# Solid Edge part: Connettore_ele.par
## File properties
Author: f_grande
Template: Normal.par
Last saved by: f_grande
Revision: 2
Application: Solid Edge
Material: PVC
Stile della faccia: Marroncino
Stile di riempimento: ANSI34(Plastica)
Stile virtuale: Marroncino (lucido)
Coef. of Thermal Exp: 0.0
Thermal Conductivity: 1.5
Specific Heat: 0.0
Modulus of Elasticity: 2757902.8
Poisson's Ratio: 0.4
Yield Stress: 6894757.0
Ultimate Stress: 0.0
Elongation: 0.0
Tipo di contenuto documento: 0
Densità: 1385,000 kg/m^3
Precisione: 0,990
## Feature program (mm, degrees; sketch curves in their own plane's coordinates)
sketch for "unnamed Protrusion 1" plane through (0, 0, 0) normal (0, 0, 1) x-axis (1, 0, 0)
  circle centre (0, 0) radius 10
extrude "unnamed Protrusion 1" add finite 10 along +normal
sketch for "unnamed RevolvedProtrusion 1" plane through (0, 0, 0) normal (0, -1, 0) x-axis (1, 0, 0)
  line (5.0499, 10) -> (12.8549, 10)
  line (12.8549, 14) -> (12.8549, 10)
  line (12.8549, 14) -> (9.6383, 14)
  arc centre (-66.7577, 14) radius 76.3959 from (9.6383, 14) to (8.61, 26.4924) ccw
  arc centre (7.8299, 26.5908) radius 0.7862 from (8.61, 26.4924) to (7.0499, 26.4924) ccw
  line (7.0499, 26.4924) -> (7.0499, 17.0772)
  line (7.0499, 17.0772) -> (6.0499, 17.0772)
  line (6.0499, 17.0772) -> (6.0499, 25.7212)
  line (6.0499, 25.7212) -> (5.0499, 25.7212)
  line (5.0499, 25.7212) -> (5.0499, 10)
revolve "unnamed RevolvedProtrusion 1" add full turn 360 deg
thread "unnamed Thread 1"
sketch for "ExtrudedCutout_1" plane through (0, 0, 10) normal (0, 0, 1) x-axis (0, -1, 0)
  circle centre (0, 0) radius 5.0499
extrude "ExtrudedCutout_1" cut finite 135 along -normal
chamfer "Smusso_1" setback 4
sketch for "ExtrudedProtrusion_2" plane through (0, 0, 8) normal (0, 0, -1) x-axis (1, 0, 0)
extrude "ExtrudedProtrusion_2" add finite 5 along +normal
fillet "Rotondo_2" radius 1
sketch for "ExtrudedCutout_2" plane through (0, 0, 3) normal (0, 0, -1) x-axis (1, 0, 0)
extrude "ExtrudedCutout_2" cut finite 135 along -normal
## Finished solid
Body 1: solid body, 26 faces, 43 edges, 18 vertices.
  Faces by surface: plane 12, cylinder 11, torus 2, cone 1
  Edges by curve: line 24, circle 13, ellipse 6
Bounding box of the edges (mm; curved faces can reach further): 27.920 x 25.710 x 26.492, from (-13.9203, -12.8549, 0) to (14, 12.8549, 26.4924).
Cylindrical faces by radius (mm): R1 x6, R6.0499 x1, R7.0499 x1, R10 x2, R12.8549 x1
Conical faces (half-angle, radius in mm at the cone's reference point): 45 deg R9.0499 x1
Toroidal faces (ring radius, tube radius in mm): R-66.7577 r76.3959 x1, R7.8299 r0.7862 x1
Planar faces by outward normal: +y 1, +z 3, -y 1, -z 3, oblique 4
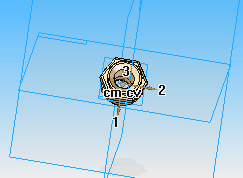
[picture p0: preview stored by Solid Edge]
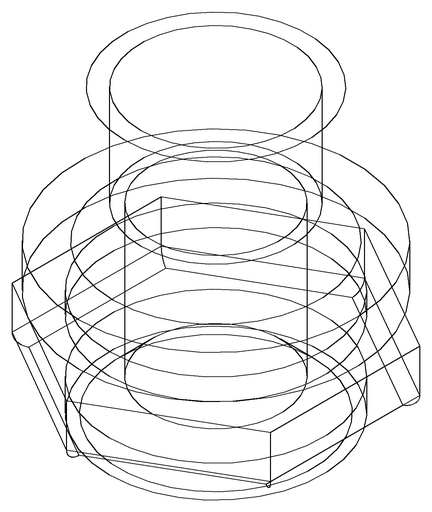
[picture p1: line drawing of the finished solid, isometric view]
